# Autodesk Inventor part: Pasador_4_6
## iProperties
Company: COMGRAP
Created: 2008-01
Part Number: Pasador_4_6
Material: ABS Plastic
Document SubType Name: Modeling
Designer: eruiz-tagle
Mass: 0.504033 g
Surface Area: 5.95458 cm^2
Volume: 0.475503 cm^3
Density: 1.06 g/cm^3
Title: CURSO INVENTOR
Author: Esteban
Comments: Esta pieza fue creada en el curso de inventor
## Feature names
1. Derived Body1 [Tagging]
